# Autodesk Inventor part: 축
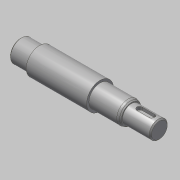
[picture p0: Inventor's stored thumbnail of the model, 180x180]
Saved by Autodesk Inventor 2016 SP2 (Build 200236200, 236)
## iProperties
Created: 2016-06
Part Number: 축
Material: 강철, 연강
Document SubType Name: Modeling
Designer: mduedu
Density: 7.86 g/cm^3
Appearance: 강철
Author: mduedu
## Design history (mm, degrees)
sketch "스케치1"
  geometry: L1 (-62, 0)-(62, 0); L2 (-62, 0)-(-62, 10); L3 (-62, 10)-(-45, 10); L4 (-45, 10)-(-45, 12); L5 (-45, 12)-(9, 12); L6 (9, 12)-(9, 10); L7 (9, 10)-(37, 10); L8 (37, 10)-(37, 8); L9 (37, 8)-(62, 8); L10 (62, 8)-(62, 0); 2 further points
  constraints: 20 end point, 5 parallel, 2 perpendicular, 1 coincident, 1 collinear, 1 horizontal, 1 midpoint, 1 vertical
  dimensions: "d0" = 124 distance of L1.start L1.end; "d2" = 16 diameter of L9 L1; "d3" = 20 diameter of L7 L1; "d4" = 24 diameter of L5 L1; "d5" = 20 diameter of L3 L1; "d6" = 17 distance of L2.end L3.end; "d7" = 25 distance of L8.end L9.end; "d8" = 53 distance from line of L5.end L10
revolve "회전1" sketch "스케치1" stored, may be unused: angle "d9" = 90 deg
chamfer "모따기1" distance "d10" = 2; stored, may be unused: second distance "d11" = 2, angle "d12" = 30 deg
fillet "모깎기1" dims "d13" = 4
node "작업 평면1"
sketch "스케치2"
  geometry: L1 (-5, 2.5)-(6, 2.5); L2 (6, -2.5)-(-5, -2.5); L3 (-5, 0)-(6, 0); L4 (-12.5, 8.845)-(-12.5, -8.845) reference; A1 r 2.5 centre (-5, 0) between (-5, 2.5) and (-5, -2.5); A2 r 2.5 centre (6, 0) between (6, -2.5) and (6, 2.5); 1 further point
  constraints: 6 end point, 4 point on circle, 3 tangent, 2 centre point, 2 parallel, 1 horizontal, 1 horizontal alignment
  dimensions: "d14" = 5 distance edge to line of A1 L4; "d15" = 5 distance between parallel lines of L2 L1; "d16" = 16 dimension on A2 A1
extrude "돌출1" cut sketch "스케치2" distance "d17" = 3; taper "d18" = 0 deg
chamfer "모따기2" distance "d19" = 1; stored, may be unused: second distance "d20" = 2, angle "d21" = 30 deg
sketch "스케치3"
  geometry: L1 (-37, -8)-(-61, -8) reference; L2 (-62, -7)-(-62, 7) reference; L3 (-38.5, -8)-(-40, -6.5); L4 (-40, -6.5)-(-40, -8); L5 (-38.5, -8)-(-40, -8); 1 further point
  constraints: 6 end point, 2 point on line, 1 collinear, 1 vertical
  dimensions: "d22" = 45 deg angle of L4 L3; "d23" = 22 distance between parallel lines of L2 L4; "d24" = 3 diameter of L3.start L4
revolve "회전2" stored, may be unused: angle "d25" = 90 deg
node "작업점1"
sketch "스케치4"
  geometry: 1 further point
hole "구멍1" sketch "스케치4" at (0, 0) diameter "d26" = 3.242; stored, may be unused: countersink angle "d30" = 90 deg, drill point angle "d32" = 120 deg; dims "d27" = 8, "d28" = 4, "d29" = 2, "d31" = 11
chamfer "모따기3" distance "d33" = 2; stored, may be unused: second distance "d34" = 2, angle "d35" = 30 deg
node "솔리드1"
